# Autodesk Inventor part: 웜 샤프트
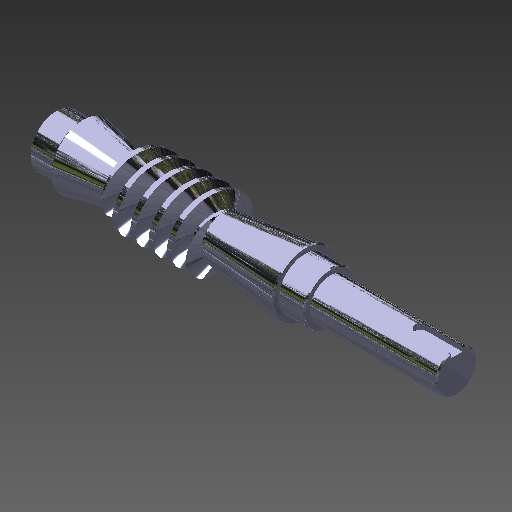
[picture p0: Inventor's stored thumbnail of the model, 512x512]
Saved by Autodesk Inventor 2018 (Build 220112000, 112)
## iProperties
Created: 2013-01
Part Number: 웜 샤프트
Material: 탄소강
Document SubType Name: Modeling
Designer: 한국산업디자인학원[gmhk.co.kr]
Categories: <?xml version="1.0" encoding="UTF-16"?> <MemberInstance><Categories><FamilyTemplate><FamilyTemplateParameter ValueType="xs:double" Id="1" ObjectReferenceKey="da
Density: 7.87 g/cm^3
Mass: 4106.37 g
Surface Area: 646.884 cm^2
Volume: 521.775 cm^3
Appearance: _시험-파란색 크롬
CustomPartVersion: 1
Author: 한국산업디자인학원[gmhk.co.kr]
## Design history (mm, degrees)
body "Solid1"
extrude "기본 본체" new body stored distance "d6" = 80 (= da_b); taper "d7" = 0 deg
chamfer "Chamfer1" distance "d8" = 4.00367 (= fd_cham1); stored, may be unused: second distance "d9" = 11 (= 0.5 x fd_cham2), angle "d47" = 45 deg
chamfer "Chamfer2" distance "d10" = 4.00367 (= fd_cham1); stored, may be unused: second distance "d11" = 11 (= 0.5 x fd_cham2), angle "d48" = 45 deg
sketch "톱니 스케치"
  geometry: L1 (0, 21.74)-(0, 10.96) reference; L2 (-60.834, 30.3)-(-56.721, 19); L3 (-53.235, 19)-(-49.122, 30.3); L4 (-50.535, 0)-(-37.455, 0) reference; L5 (-60.834, 30.3)-(-54.978, 30.3); L6 (-54.978, 30.3)-(-49.122, 30.3); L7 (-56.721, 19)-(-54.978, 19); L8 (-54.978, 19)-(-53.235, 19); L9 (-54.978, 25)-(-51.051, 25); L10 (-54.978, 30.3)-(-54.978, 19)
  constraints: 16 end point, 3 equal length, 3 parallel, 2 collinear, 2 point on line
  dimensions: "d24" = 110 deg angle of L7 L2 (computed from da_alfat); "d25" = 54.97787 distance from line of L1 L5.end (= fd_dist); "d26" = 3.92699 distance of L9.start L9.end (= 0.25 x da_px); "d27" = 19 distance between parallel lines of L4 L7 (= 0.5 x da_df); "d28" = 25 distance between parallel lines of L4 L9 (= 0.5 x da_d); "d29" = 30.3 distance between parallel lines of L4 L5 (= 0.505 x da_da)
feature "톱니" pitch "d30" = 31.41593 (computed from da_px, da_z); turns "d32" = 8 (= fd_n); dims "d31" = 10, "d33" = 0, angle "d34" = 90 deg, angle "d35" = 90 deg, "d36" = 0, "d37" = 0, "d70" = 10, "da_rightdir" = 0 [user parameter]
pattern_circular "톱니 패턴" dims angle "d46" = 360 deg, "da_rightdir" = 0 [user parameter]
feature "왼쪽 톱니" pitch "d62" = 31.41593 (computed from da_px, da_z); turns "d64" = 8 (= fd_n); dims "d63" = 10, "d65" = 0, angle "d66" = 90 deg, angle "d67" = 90 deg, "d68" = 0, "d69" = 0, "d76" = 10, "da_rightdir" = 0 [user parameter]
pattern_circular "왼쪽 톱니 패턴" dims angle "d73" = 360 deg, "da_rightdir" = 0 [user parameter]
sketch "스케치8"
  geometry: C1 r 18.99 at (0, 0); A1 r 19 centre (0, 0) between (9.02, 16.723) and (-3.823, 18.611) reference; A2 r 19 centre (0, 0) between (-3.823, 18.611) and (-9.02, -16.723) reference; A3 r 19 centre (0, 0) between (-9.02, -16.723) and (3.823, -18.611) reference; A4 r 19 centre (0, 0) between (3.823, -18.611) and (9.02, 16.723) reference; 1 further point
  constraints: 1 centre point, 1 coincident
  dimensions: "d87" = 0.01 radial gap between concentric circles of C1 A2
node "작업 평면10"
extrude "돌출2" join sketch "스케치8" distance "d88" = 1; taper "d89" = 0 deg
mirror "대칭1"
revolve "회전1" stored, may be unused: angle "d90" = 90 deg
chamfer "모따기3" distance "d91" = 1; stored, may be unused: second distance "d92" = 2, angle "d93" = 45 deg
node "작업 평면11"
sketch "스케치9"
  geometry: L1 (-54.5, -16.5)-(-54.5, 16.5) reference; L2 (-54.5, 5)-(-23.5, 5); L3 (-23.5, -5)-(-54.5, -5); A1 r 5 centre (-23.5, 0) between (-23.5, -5) and (-23.5, 5); 2 further points
  constraints: 4 end point, 2 perpendicular, 2 point on circle, 2 point on line, 2 tangent, 1 centre point, 1 horizontal alignment, 1 midpoint
  dimensions: "d94" = 10 distance between parallel lines of L3 L2; "d96" = 36 dimension on A1 L1
extrude "돌출3" cut sketch "스케치9" distance "d97" = 5; taper "d98" = 0 deg
node "기본 본체 스케치" dims "d5" = 60 (= da_da)
sketch "Sketch5"
  geometry: C1 r 30 at (0, 0) reference; C2 r 25 at (0, 0)
  constraints: 1 centre point, 1 coincident
  dimensions: "d59" = 50 diameter of C2 (= da_d)
body "Srf1"
sketch "스케치7"
  geometry: L1 (40, 18.611)-(40, -16.723) reference; L2 (40, 19)-(40, 16.723) reference; L3 (40, 18.611)-(40, 16.723) reference; L4 (40, -16.723)-(40, 18.611) reference; L5 (40, -18.611)-(40, -16.723) reference; L6 (40, 16.723)-(40, -18.611) reference; L7 (40, -16.723)-(40, -19) reference; L8 (41, 0)-(241, 0); L9 (110, 27.5)-(110, 22.5); L10 (110, 22.5)-(132, 22.5); L11 (132, 22.5)-(132, 17.5); L12 (132, 17.5)-(241, 17.5); L13 (241, 17.5)-(241, 0); L14 (127.9, 22.5)-(111.1, 22.5) reference; L15 (110, -41.4)-(110, 41.4) reference; L16 (-40, -16.723)-(-40, 18.611) reference; L17 (-41, 0)-(-105, 0); L18 (25.305, 19)-(-40, 19) reference; L19 (-82, 27.5)-(-82, 22.5); L20 (-82, 22.5)-(-105, 22.5); L21 (-105, 22.5)-(-105, 0); L22 (-82, 41.4)-(-82, -41.4) reference; L23 (41, 18.99)-(41, -18.99) reference; L24 (41, 0)-(41, 18.99); L25 (41, 18.99)-(110, 27.5); L26 (-41, 18.99)-(-41, -18.99) reference; L27 (-41, 0)-(-41, 18.99); L28 (-41, 18.99)-(-82, 27.5); 1 further point
  constraints: 30 end point, 7 collinear, 7 perpendicular, 2 midpoint, 1 horizontal, 1 horizontal alignment, 1 parallel, 1 point on line, 2 other
  dimensions: "d82" = 35 diameter of L12 L8; "d83" = 55 diameter of L9.start L8; "d84" = 22 distance of L9.end L10.end; "d85" = 200 distance of L8.start L8.end; "d86" = 64 distance of L17.start L17.end
node "투영된 루프1"
node "참조1"
node "참조2"
node "투영된 루프2"
feature "피치 지름" dims "d60" = 10, "d61" = 0
other parameters: "da_b" = 80 [user parameter; used in 3 equation terms], "da_df" = 38 [user parameter; used in 2 equation terms], "fd_cham2" = 22 (= da_da - da_df) [user parameter; used in 3 equation terms], "fd_cham1" = 4.00367 (= 0.181985 x fd_cham2) [user parameter; used in 2 equation terms], "da_d" = 50 [user parameter; used in 2 equation terms], "da_px" = 90 deg [user parameter; used in 5 equation terms], "fd_dist" = 54.97787 (computed from da_b, da_px) [user parameter; used in 1 equation term], "fd_n" = 8 (computed from da_b, da_px) [user parameter; used in 2 equation terms], "da_alfat" = 20 deg [user parameter; used in 1 equation term], "d12" = 110 deg (derived), "d14" = 3.1425 (derived), "d50" = 0, "d54" = 0, "d56" = 0, "d77" = 0, "d80" = 0
